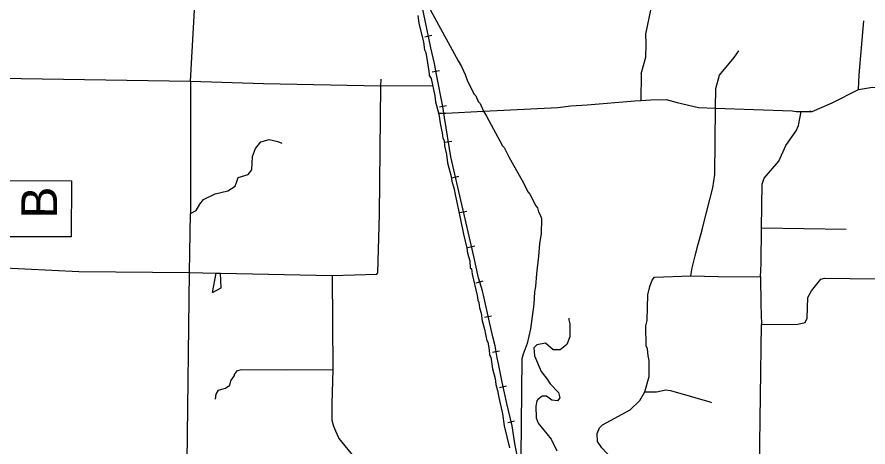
# Model space of a CAD drawing. Extents: x 299354 to 1325680, y 96128 to 228242.
# Drawn here: x 341858 to 365592, y 201720 to 213706 of the extents above; entities that cross this region are included whole.
import ezdxf

# ---------------------------------------------------------------- set-up
doc = ezdxf.new("R2010")
doc.units = 0
for name, color, linetype in [('Level 13', 7, 'Continuous'), ('Level 2', 7, 'Continuous'), ('Level 4', 7, 'Continuous'), ('Level 45', 7, 'Continuous'), ('Level 57', 7, 'Continuous')]:
    doc.layers.add(name, color=color, linetype=linetype)

msp = doc.modelspace()

# ---------------------------------------------------------------- linework, layer by layer
at = {"layer": 'Level 13'}
msp.add_line((342475, 208395), (342475, 208395), dxfattribs=at)
msp.add_lwpolyline([(343369, 207574), (341619, 207581), (341625, 209151), (343375, 209143)], close=True, dxfattribs=at)
at = {"layer": 'Level 2'}
for points in [[(353038, 213746), (353069, 213537), (353195, 213006), (353226, 212787), (353258, 212720), (353304, 212425), (353335, 212256), (353356, 212123)], [(353356, 212123), (353356, 212073), (353405, 211988), (353515, 211508), (353529, 211340), (353625, 210994), (353671, 210691), (353719, 210482), (353734, 210332), (353767, 210265), (353782, 210115), (353838, 209873), (353869, 209639), (353966, 209263), (353981, 209130), (354046, 208904), (354078, 208754), (354238, 208011), (354310, 207652), (354406, 207259), (354422, 207126), (354486, 206908), (354501, 206717), (354534, 206683), (354550, 206533), (354694, 205940), (354710, 205815), (354742, 205748), (354758, 205598), (354806, 205447), (354829, 205239), (354894, 205005), (354958, 204679), (354991, 204646), (355022, 204429), (355038, 204287), (355070, 204220), (355117, 203903), (355198, 203627), (355213, 203460), (355262, 203293), (355293, 203101), (355398, 202642), (355445, 202308), (355589, 201698)], [(365331, 211685), (365715, 211749), (368008, 211695)], [(363732, 211075), (364032, 211072), (364593, 211317), (365331, 211685)], [(354871, 211084), (356944, 211186), (357303, 211233), (357762, 211262), (359089, 211367), (359256, 211382)], [(359256, 211382), (359540, 211396)], [(359540, 211396), (359965, 211409), (360273, 211323), (360864, 211184), (361339, 211163)], [(353607, 211025), (353815, 211023), (354871, 211084)], [(361339, 211163), (363474, 211094), (363590, 211076), (363732, 211075)]]:
    msp.add_lwpolyline(points, dxfattribs=at)
at = {"layer": 'Level 4'}
for p, q in [((353230, 213156), (353426, 213196)), ((353441, 212181), (353638, 212217)), ((353637, 211199), (353833, 211238)), ((353790, 210215), (353988, 210245)), ((353985, 209227), (354180, 209272)), ((354210, 208253), (354405, 208298)), ((354435, 207279), (354630, 207324)), ((354666, 206300), (354858, 206356)), ((354900, 205335), (355096, 205378)), ((355122, 204364), (355318, 204400)), ((355318, 203380), (355514, 203422)), ((355543, 202403), (355737, 202451))]:
    msp.add_line(p, q, dxfattribs=at)
for points in [[(346701, 211921), (346826, 214237), (346868, 214947), (346930, 217194)], [(359266, 212121), (359400, 212585), (359406, 212961), (359393, 213228), (359550, 213986), (359550, 216758)], [(352813, 214724), (353062, 214433), (353146, 214381), (353444, 213794), (354158, 212484), (354257, 212323), (354357, 212102)], [(353501, 212408), (353396, 212843), (353285, 213386), (353041, 214591)], [(355892, 201062), (355740, 201814), (355670, 202306), (355517, 202932), (355389, 203525), (355285, 204035), (355254, 204201), (355190, 204544), (355126, 204794), (355013, 205287), (354885, 205872), (354837, 206072), (354732, 206431), (354644, 206815), (354604, 206991), (353954, 209805), (353785, 210904), (353736, 211212), (353558, 212104), (353501, 212408), (353396, 212843), (353285, 213386), (353041, 214591)], [(365349, 212093), (365473, 213603)], [(361453, 212089), (361864, 212576), (361994, 212766)], [(353558, 212104), (353501, 212408)], [(341365, 212002), (346701, 211921)], [(352004, 211789), (352015, 211978)], [(355670, 202306), (355517, 202932), (355389, 203525), (355285, 204035), (355254, 204201), (355190, 204544), (355126, 204794), (355013, 205287), (354885, 205872), (354837, 206072), (354732, 206431), (354644, 206815), (354604, 206991), (353954, 209805), (353785, 210904), (353736, 211212), (353558, 212104)], [(354357, 212102), (354419, 211917), (354605, 211559), (354656, 211506), (354724, 211349), (354774, 211297), (354871, 211084)], [(359266, 212121), (359256, 211382)], [(361339, 211163), (361353, 211710), (361453, 212089)], [(365331, 211685), (365349, 212093)], [(346701, 211921), (346701, 208229)], [(346701, 211921), (348736, 211852), (352004, 211789)], [(350646, 206502), (351889, 206540), (351923, 206573), (351971, 208198), (352004, 211789)], [(352004, 211789), (353447, 211793)], [(354871, 211084), (354949, 210946), (355400, 210117), (355449, 210067), (355580, 209790), (355950, 209145), (356114, 208819), (356163, 208768), (356327, 208442), (356376, 208391), (356400, 208275), (356450, 208191), (356482, 208090), (356478, 207665), (356426, 207391), (356406, 207041), (356343, 206550), (356323, 206192), (356288, 206042), (356268, 205701), (356178, 205010), (356091, 204602), (355972, 204303), (355937, 204179), (355912, 201454)], [(360654, 206494), (360689, 206711), (360776, 207052), (360845, 207334), (360966, 207775), (361001, 207933), (361269, 208947), (361322, 209313), (361339, 211163)], [(362626, 207826), (362637, 209051), (362697, 209218), (363102, 209689), (363298, 210129), (363585, 210535), (363653, 210684), (363732, 211075)], [(346701, 208229), (346852, 208311), (346953, 208493), (347063, 208617), (347381, 208781), (347741, 208861), (347942, 208993), (347993, 209117), (348028, 209234), (348304, 209315), (348405, 209447), (348425, 209822), (348510, 210038), (348654, 210228), (348888, 210293), (349129, 210240), (349246, 210189)], [(346669, 206588), (346701, 208229)], [(362617, 206835), (362626, 207826)], [(362626, 207826), (364986, 207788)], [(362597, 206460), (362617, 206835)], [(341316, 206719), (343583, 206616), (346669, 206588)], [(346603, 201305), (346669, 206588)], [(346669, 206588), (347411, 206564)], [(347306, 206023), (347411, 206564)], [(347306, 206023), (347549, 206155), (347536, 206563)], [(347411, 206564), (347536, 206563)], [(347536, 206563), (350646, 206502)], [(350646, 206502), (350664, 203876)], [(359365, 203256), (359486, 203688), (359490, 204130), (359457, 204263), (359443, 204455), (359410, 204539), (359398, 205097), (359433, 205247), (359456, 205963), (359509, 206196), (359569, 206371), (359636, 206454), (360654, 206494)], [(360654, 206494), (361413, 206471), (362597, 206460)], [(362597, 206460), (362606, 205693)], [(362618, 205135), (363636, 205142), (363844, 205190), (363896, 205315), (363918, 205890), (364019, 206072), (364281, 206395), (364381, 206427), (367925, 206378)], [(362606, 205693), (362618, 205135)], [(362565, 201160), (362618, 205135)], [(347395, 203056), (347413, 203189), (347481, 203305), (347673, 203362), (347791, 203444), (347825, 203560), (347927, 203709), (347927, 203743), (348011, 203850), (348120, 203883), (349371, 203871), (350664, 203876)], [(350664, 203876), (350638, 202927), (350634, 202468), (350682, 202301), (350829, 201958), (351250, 201446), (351365, 201203), (351396, 201036), (351511, 200785), (351734, 200558), (352015, 200256)], [(358639, 197837), (358642, 198096), (358635, 201021), (358603, 201179), (358538, 201297), (358166, 201692), (358051, 201876), (358036, 202093), (358105, 202251), (358189, 202333), (358960, 202751), (359229, 203015), (359365, 203256)], [(359365, 203256), (359690, 203253), (359957, 203317), (360082, 203299), (361180, 202981), (361230, 202964)], [(356352, 198954), (356276, 199300), (356196, 199693), (356116, 200060), (356021, 200569), (355892, 201062), (355740, 201814), (355670, 202306)]]:
    msp.add_lwpolyline(points, dxfattribs=at)
at = {"layer": 'Level 45'}
for points in [[(360887, 211161), (360888, 211162)], [(360888, 211162), (360888, 211161)], [(363976, 211078), (363981, 211095)], [(363981, 211095), (363986, 211077)]]:
    msp.add_lwpolyline(points, dxfattribs=at)
at = {"layer": 'Level 57'}
msp.add_lwpolyline([(357248, 205315), (357249, 205267), (357281, 205150), (357278, 204792), (357193, 204576), (357008, 204427), (356816, 204429), (356601, 204614), (356359, 204567), (356275, 204484), (356289, 204259), (356477, 203824), (356642, 203614), (356724, 203480), (356964, 203236), (356996, 203086), (356928, 203003), (356770, 203021), (356621, 203139), (356504, 203140), (356386, 203041), (356353, 203008), (356326, 202858), (356340, 202533), (356397, 202383), (356760, 201938), (356915, 201611)], dxfattribs=at)

# ---------------------------------------------------------------- texts
at = {"layer": 'Level 13'}
msp.add_text('B', height=1000, rotation=89.767, dxfattribs=at).set_placement((342974, 208086))

doc.saveas('drawing.dxf')
